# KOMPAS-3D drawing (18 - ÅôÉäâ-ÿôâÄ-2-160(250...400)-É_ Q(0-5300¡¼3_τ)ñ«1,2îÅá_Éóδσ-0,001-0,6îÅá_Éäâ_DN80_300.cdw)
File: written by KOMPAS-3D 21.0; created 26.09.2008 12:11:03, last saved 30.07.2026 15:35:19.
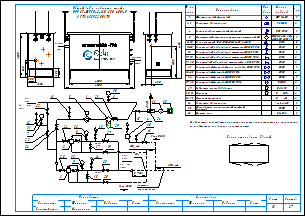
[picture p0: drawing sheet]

Sheets 1-2: A3, landscape

Document properties: Наименование: Макро:21; Автор: RaskoAdmin; Форматы листов документа: 2xA3; Полное имя файла: \\ur38nt01\Departments\КТО\КБ ПУРДГ\Заявки\Прайс-лист на типовые шкафы ГРПШ\ПУРДГ_стандарт_30_04_2026\ПУРДГ с РДГ(Н, В)\ПУРДГ-ШУГО-2-160(250...400)-Р_ Q(0-5300нм3_ч)до1,2МПа_Рвых-0,001-0,6МПа_РДГ_DN80_300.cdw

Title block, sheet 1: Наименование: Пункт учета газа / ПУГ-Ш-400-Р / ЛГТИ.485922.001ТУ; designation: ЛГТИ.03.4411141; sheet number: 1; Количество листов документа: 2; organisation: ООО "ЭЛЬСТЕР Газэлектроника"; Форматы листов документа: A3; stored path: C:\Рабочие документы\Компас\ПУГ\Схема.cdw; Разработал: Устинов; Проверил: Кошкин; Утвердил: Кошкин
Title block, sheet 2: sheet number: 2; stored path: D:\Рабочие документы\Заявки\ПУРДГ\ПУРДГ-ШУЭО-2-100-Р 4411220.cdw; designation, second copy: ЛГТИ.03.4411141-

Views: Вид 1, Вид 2
Referenced files: wcvoit.frw
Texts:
  Normal
  № на
  схеме
  Усл.
  обозн.
  Марка
  (модель)
  Кол.
  Фильтр газовый фланцевый
  ФГ 16-50
  Регулятор давления газа
  РДГ-50
  Клапан предохранительный сбросной
  ПСК DN25
  Измерительный комплекс с ротационным счетчиком Ду50
  СГ-ЭК-Р-(0,2...2,0)-
  Кран кнопочный VE-РАСКО-НЗ-1,6-G1/2-М20
  DN15
  Кран шаровой "под приварку" штуцерный DN20 PN16
  Кран шаровой "под приварку" штуцерный DN25 PN16
  DN20
  DN25
  Кран шаровой "под приварку" штуцерный DN15 PN16
  Кран шаровой "под приварку" штуцерный п/п DN20 PN16
  Кран шаровой фланцевый с мех. приводом DN50 PN16
  Кран шаровой фланцевый DN50 PN16
  Кран шаровой фланцевый DN80 PN16
  Кран шаровой фланцевый DN300 PN16
  DN50
  DN80
  DN300
  Индикатор перепада давления
  Манометр
  Манометр-напоромер
  Обогреватель газогорелочный шкафной
  (Эльтон")
  Счетчик газа
  Delta 15
  0...     МПа
  0...     кПа
  Venio-A-15
  ОГШН
  BK-G1,6
  Выход газа
  Вход газа
  logo-rasko-ge.png
  DN 1
  местное
  сопротивление
  Римп DN20
  Выход
  газа
  Р=     кПа
  Вход
  Р=       МПа
  PDI
  Схема открывания дверей
  Предприятие изготовитель может заменять комплектующие на аналогичные,
  не ухудшающие заявленных характеристик.
  Общий вид и габариты шкафа
  ПУРДГ-ШУГО-2-160(250...400)-Р
  Должность
  Конструктор
  Фамилия
  Подпись
  Дата
  Согласовано
  Максимкин
  Лист
  Листов
  POLYLINE_STYLE_0.18_RGB_0_0_0
  POLYLINE_STYLE_0.50_RGB_0_0_0
  POLYLINE_STYLE_0.34_RGB_0_0_0
  PHANTOM_RGB_0_0_0_SC_1_THICK_0.18
  K5LT_THIN_RGB_0_0_0_THICK_0.18
  K5LT32769_RGB_0_0_0_THICK_0.18
  K5LT12_RGB_0_0_0_SC_1_THICK_0.18
  K5LT_DASHED_RGB_0_0_0_SC_1_THICK_0.18
  ACISOTGL_RGB_0_0_0_SC_0.8_THICK_0.25
  CONTINUOUS_RGB_0_127_31_THICK_0.3
  CONTINUOUS_RGB_0_0_255_THICK_0.35
  CONTINUOUS_RGB_255_0_0_THICK_0.35
  POLYLINE_STYLE_0.25_RGB_0_0_0
  CONTINUOUS_RGB_0_0_0_THICK_0.5
  POLYLINE_STYLE_0.35_RGB_0_0_255
  CONTINUOUS_RGB_0_0_0_THICK_0.4
  CONTINUOUS_RGB_0_0_0_THICK_0.35
  НЕВИДИМАЯ_RGB_0_0_0_SC_0.3_THICK_0.25
  СONTINUOUS_RGB_0_0_0_THICK_0.25
  ОСЕВАЯ2_RGB_248_153_30_SC_0.3_THICK_0.25
  Без оформления
Dimensions and other numbers on the sheet: 1; 2, 3; 2; 4; 5; -160(250; 400)/1,6; 6-10; 11-15; 16; 17, 18; 19, 20; 21; 22-25; 26; 27, 28; 29; 30, 31; 32, 33; 34; 35; 36; 1500; 450; 500; 1200; 550; 305; 4000; 4130; 2000; 4300; 5,,,7DN 1; 7; 31; 12; 22; 23; 24; 11; 6; 30; 32; 8; 13; 27; 19; 10; 25; 33; 9; 3; 14; 28; 20; 17; 18; 15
